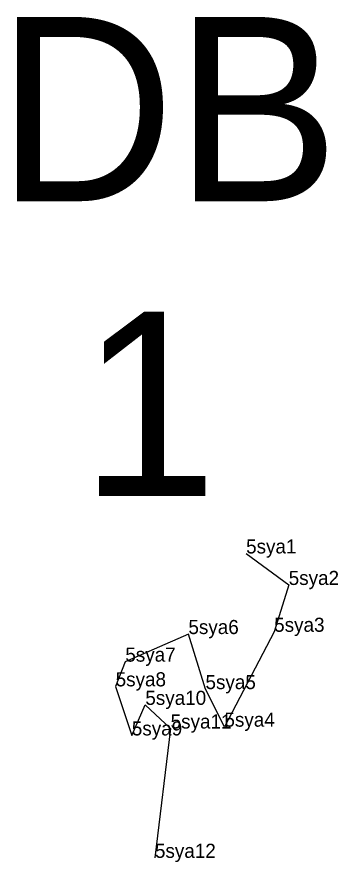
# Model space of a CAD drawing. Extents: x 2072529 to 2268796, y 436423 to 470397.
# Drawn here: x 2198684.4 to 2198798.2, y 454022.4 to 454322 of the extents above; entities that cross this region are included whole.
import ezdxf

# ---------------------------------------------------------------- set-up
doc = ezdxf.new("R2010")
doc.units = 0
for name, color, linetype in [('Default', 7, 'Continuous'), ('Exist Environmental Wetland Boundary Cogo Point CELL', 7, 'Continuous'), ('Exist Hydro Jurisdictional Stream or Body of Water NEU Mitigable', 7, 'Continuous'), ('Exist Hydro Jurisdictional Stream or Body of Water NEU Mitigable Cogo Comment', 7, 'Continuous')]:
    doc.layers.add(name, color=color, linetype=linetype)

msp = doc.modelspace()

# ---------------------------------------------------------------- linework, layer by layer
at = {"layer": 'Exist Environmental Wetland Boundary Cogo Point CELL'}
for p, q in [((2198765.62, 454131.78), (2198765.62, 454131.78)), ((2198765.62, 454131.78), (2198765.62, 454131.78)), ((2198780.71, 454120.61), (2198780.71, 454120.61)), ((2198780.71, 454120.61), (2198780.71, 454120.61)), ((2198745.18, 454103.21), (2198745.18, 454103.21)), ((2198745.18, 454103.21), (2198745.18, 454103.21)), ((2198775.56, 454104.01), (2198775.56, 454104.01)), ((2198775.56, 454104.01), (2198775.56, 454104.01)), ((2198722.83, 454093.42), (2198722.83, 454093.42)), ((2198722.83, 454093.42), (2198722.83, 454093.42)), ((2198719.4, 454084.67), (2198719.4, 454084.67)), ((2198719.4, 454084.67), (2198719.4, 454084.67)), ((2198751.23, 454083.69), (2198751.23, 454083.69)), ((2198751.23, 454083.69), (2198751.23, 454083.69)), ((2198729.92, 454078.11), (2198729.92, 454078.11)), ((2198729.92, 454078.11), (2198729.92, 454078.11)), ((2198738.88, 454069.73), (2198738.88, 454069.73)), ((2198738.88, 454069.73), (2198738.88, 454069.73)), ((2198757.94, 454070.37), (2198757.94, 454070.37)), ((2198757.94, 454070.37), (2198757.94, 454070.37)), ((2198725.14, 454067.27), (2198725.14, 454067.27)), ((2198725.14, 454067.27), (2198725.14, 454067.27)), ((2198733.32, 454023.88), (2198733.32, 454023.88)), ((2198733.32, 454023.88), (2198733.32, 454023.88))]:
    msp.add_line(p, q, dxfattribs=at)
at = {"layer": 'Exist Hydro Jurisdictional Stream or Body of Water NEU Mitigable'}
msp.add_lwpolyline([(2198765.62, 454131.78), (2198780.71, 454120.61), (2198775.56, 454104.01), (2198757.94, 454070.37), (2198751.23, 454083.69), (2198745.18, 454103.21), (2198722.83, 454093.42), (2198719.4, 454084.67), (2198725.14, 454067.27), (2198729.92, 454078.11), (2198738.88, 454069.73), (2198733.32, 454023.88)], dxfattribs=at)
msp.add_lwpolyline([(2198765.62, 454131.78), (2198780.71, 454120.61), (2198775.56, 454104.01), (2198757.94, 454070.37), (2198751.23, 454083.69), (2198745.18, 454103.21), (2198722.83, 454093.42), (2198719.4, 454084.67), (2198725.14, 454067.27), (2198729.92, 454078.11), (2198738.88, 454069.73), (2198733.32, 454023.88)], dxfattribs=at)

# ---------------------------------------------------------------- texts
at = {"layer": 'Default'}
for s, p in [('DB', (2198677.26, 454256.65)), ('1', (2198706.82, 454152.1))]:
    msp.add_text(s, height=65.34, dxfattribs=at).set_placement(p)
at = {"layer": 'Exist Hydro Jurisdictional Stream or Body of Water NEU Mitigable Cogo Comment'}
for s, p in [('5sya1', (2198765.62, 454131.78)), ('5sya2', (2198780.71, 454120.61)), ('5sya3', (2198775.56, 454104.01)), ('5sya6', (2198745.18, 454103.21)), ('5sya7', (2198722.83, 454093.42)), ('5sya8', (2198719.4, 454084.67)), ('5sya5', (2198751.23, 454083.69)), ('5sya10', (2198729.92, 454078.11)), ('5sya11', (2198738.88, 454069.73)), ('5sya4', (2198757.94, 454070.37)), ('5sya9', (2198725.14, 454067.27)), ('5sya12', (2198733.32, 454023.88))]:
    msp.add_text(s, height=5, dxfattribs=at).set_placement(p)

doc.saveas('drawing.dxf')
